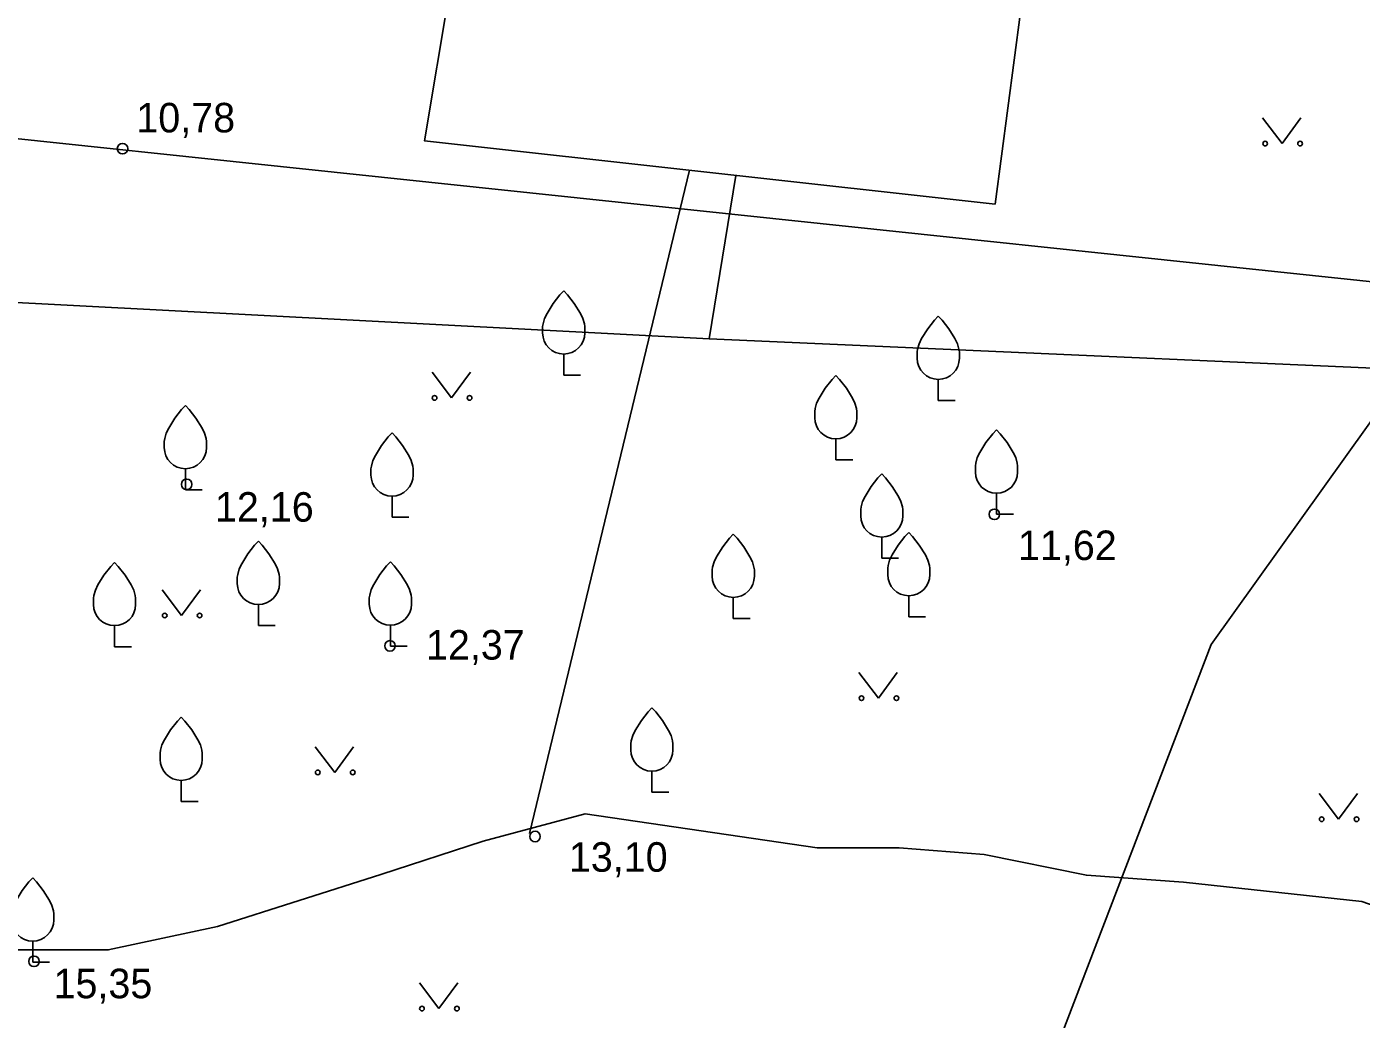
# Model space of a CAD drawing. Extents: x 713497 to 713863, y 6590062 to 6590327.
# Drawn here: x 713803.4 to 713835.04, y 6590273.77 to 6590297.3 of the extents above; entities that cross this region are included whole.
import ezdxf

# ---------------------------------------------------------------- set-up
doc = ezdxf.new("R2010")
doc.units = 0
for name, color, linetype in [('AED', 7, 'Continuous'), ('HALJASTUS', 7, 'Continuous'), ('HOONE', 7, 'Continuous'), ('KORGUS', 7, 'Continuous'), ('KPKAABEL', 7, 'Continuous'), ('PUU', 7, 'Continuous'), ('TTRASS', 7, 'Continuous')]:
    doc.layers.add(name, color=color, linetype=linetype)

msp = doc.modelspace()

# ---------------------------------------------------------------- linework, layer by layer
at = {"layer": 'AED'}
msp.add_lwpolyline([(713815.32, 6590278.17), (713819.11, 6590293.9)], dxfattribs=at)
at = {"layer": 'HALJASTUS'}
for p, q in [((713832.697, 6590295.137), (713833.16, 6590294.53)), ((713833.16, 6590294.53), (713833.606, 6590295.137)), ((713813.007, 6590289.107), (713813.47, 6590288.5)), ((713813.47, 6590288.5), (713813.916, 6590289.107)), ((713806.607, 6590283.947), (713807.07, 6590283.34)), ((713807.07, 6590283.34), (713807.516, 6590283.947)), ((713823.127, 6590281.987), (713823.59, 6590281.38)), ((713823.59, 6590281.38), (713824.036, 6590281.987)), ((713810.237, 6590280.227), (713810.7, 6590279.62)), ((713810.7, 6590279.62), (713811.146, 6590280.227)), ((713834.037, 6590279.117), (713834.5, 6590278.51)), ((713834.5, 6590278.51), (713834.946, 6590279.117)), ((713812.707, 6590274.627), (713813.17, 6590274.02)), ((713813.17, 6590274.02), (713813.616, 6590274.627))]:
    msp.add_line(p, q, dxfattribs=at)
msp.add_lwpolyline([(713835.82, 6590276.29), (713835.05, 6590276.56), (713830.82, 6590277.02), (713828.52, 6590277.18), (713826.1, 6590277.67), (713824.08, 6590277.83), (713822.14, 6590277.83), (713816.64, 6590278.64), (713814.22, 6590277.99), (713811.79, 6590277.2), (713807.92, 6590275.97), (713805.33, 6590275.41), (713802.91, 6590275.41), (713801.86, 6590275.65), (713801.29, 6590275.73), (713800.48, 6590276.13), (713798.54, 6590276.3), (713797.17, 6590276.7), (713794.83, 6590277.43), (713792.28, 6590278.01), (713788.27, 6590278.75)], dxfattribs=at)
for centre in [(713832.759, 6590294.53), (713833.588, 6590294.53), (713813.069, 6590288.5), (713813.898, 6590288.5), (713806.669, 6590283.34), (713807.498, 6590283.34), (713823.189, 6590281.38), (713824.018, 6590281.38), (713810.299, 6590279.62), (713811.128, 6590279.62), (713834.099, 6590278.51), (713834.928, 6590278.51), (713812.769, 6590274.02), (713813.598, 6590274.02)]:
    msp.add_circle(centre, 0.055, dxfattribs=at)
at = {"layer": 'HOONE'}
for points in [[(713826.357, 6590293.093), (713827.26, 6590299.933), (713814.015, 6590301.681), (713812.831, 6590294.592), (713826.357, 6590293.093)], [(713819.58, 6590289.9), (713820.21, 6590293.77)], [(713789.58, 6590291.47), (713819.58, 6590289.9)], [(713819.58, 6590289.9), (713841.05, 6590288.95)]]:
    msp.add_lwpolyline(points, dxfattribs=at)
at = {"layer": 'KORGUS'}
for centre in [(713805.67, 6590294.41), (713807.19, 6590286.45), (713826.34, 6590285.74), (713812.01, 6590282.62), (713815.45, 6590278.1), (713803.57, 6590275.14)]:
    msp.add_circle(centre, 0.125, dxfattribs=at)
at = {"layer": 'KPKAABEL'}
msp.add_lwpolyline([(713863.358, 6590307.496), (713846.983, 6590310.189), (713845.732, 6590309.62), (713844.539, 6590307.426), (713843.803, 6590302.325), (713840.539, 6590295.308), (713831.48, 6590282.65), (713817.48, 6590246.13), (713815.88, 6590242.79)], dxfattribs=at)
at = {"layer": 'PUU'}
for p, q in [((713816.13, 6590289.04), (713816.13, 6590289.54)), ((713816.53, 6590289.04), (713816.13, 6590289.04)), ((713825.01, 6590288.44), (713825.01, 6590288.94)), ((713825.41, 6590288.44), (713825.01, 6590288.44)), ((713822.58, 6590287.03), (713822.58, 6590287.53)), ((713822.98, 6590287.03), (713822.58, 6590287.03)), ((713807.16, 6590286.32), (713807.16, 6590286.82)), ((713807.56, 6590286.32), (713807.16, 6590286.32)), ((713812.06, 6590285.67), (713812.06, 6590286.17)), ((713826.39, 6590285.74), (713826.39, 6590286.24)), ((713826.79, 6590285.74), (713826.39, 6590285.74)), ((713812.46, 6590285.67), (713812.06, 6590285.67)), ((713823.67, 6590284.7), (713823.67, 6590285.2)), ((713824.07, 6590284.7), (713823.67, 6590284.7)), ((713808.89, 6590283.1), (713808.89, 6590283.6)), ((713820.15, 6590283.27), (713820.15, 6590283.77)), ((713824.31, 6590283.31), (713824.31, 6590283.81)), ((713820.55, 6590283.27), (713820.15, 6590283.27)), ((713824.71, 6590283.31), (713824.31, 6590283.31)), ((713805.48, 6590282.6), (713805.48, 6590283.1)), ((713809.29, 6590283.1), (713808.89, 6590283.1)), ((713812.02, 6590282.61), (713812.02, 6590283.11)), ((713805.88, 6590282.6), (713805.48, 6590282.6)), ((713812.42, 6590282.61), (713812.02, 6590282.61)), ((713807.06, 6590278.93), (713807.06, 6590279.43)), ((713818.22, 6590279.15), (713818.22, 6590279.65)), ((713818.62, 6590279.15), (713818.22, 6590279.15)), ((713807.46, 6590278.93), (713807.06, 6590278.93)), ((713803.54, 6590275.12), (713803.54, 6590275.62)), ((713803.94, 6590275.12), (713803.54, 6590275.12))]:
    msp.add_line(p, q, dxfattribs=at)
for points in [[(713815.63, 6590290.04), (713815.63, 6590290.19), (713815.64, 6590290.255), (713815.675, 6590290.385), (713815.735, 6590290.505), (713815.88, 6590290.74), (713816.04, 6590290.945), (713816.13, 6590291.04)], [(713816.63, 6590290.04), (713816.63, 6590290.19), (713816.62, 6590290.255), (713816.585, 6590290.385), (713816.525, 6590290.505), (713816.38, 6590290.74), (713816.22, 6590290.945), (713816.13, 6590291.04)], [(713824.51, 6590289.44), (713824.51, 6590289.59), (713824.52, 6590289.655), (713824.555, 6590289.785), (713824.615, 6590289.905), (713824.76, 6590290.14), (713824.92, 6590290.345), (713825.01, 6590290.44)], [(713825.51, 6590289.44), (713825.51, 6590289.59), (713825.5, 6590289.655), (713825.465, 6590289.785), (713825.405, 6590289.905), (713825.26, 6590290.14), (713825.1, 6590290.345), (713825.01, 6590290.44)], [(713822.08, 6590288.03), (713822.08, 6590288.18), (713822.09, 6590288.245), (713822.125, 6590288.375), (713822.185, 6590288.495), (713822.33, 6590288.73), (713822.49, 6590288.935), (713822.58, 6590289.03)], [(713823.08, 6590288.03), (713823.08, 6590288.18), (713823.07, 6590288.245), (713823.035, 6590288.375), (713822.975, 6590288.495), (713822.83, 6590288.73), (713822.67, 6590288.935), (713822.58, 6590289.03)], [(713806.66, 6590287.32), (713806.66, 6590287.47), (713806.67, 6590287.535), (713806.705, 6590287.665), (713806.765, 6590287.785), (713806.91, 6590288.02), (713807.07, 6590288.225), (713807.16, 6590288.32)], [(713807.66, 6590287.32), (713807.66, 6590287.47), (713807.65, 6590287.535), (713807.615, 6590287.665), (713807.555, 6590287.785), (713807.41, 6590288.02), (713807.25, 6590288.225), (713807.16, 6590288.32)], [(713811.56, 6590286.67), (713811.56, 6590286.82), (713811.57, 6590286.885), (713811.605, 6590287.015), (713811.665, 6590287.135), (713811.81, 6590287.37), (713811.97, 6590287.575), (713812.06, 6590287.67)], [(713812.56, 6590286.67), (713812.56, 6590286.82), (713812.55, 6590286.885), (713812.515, 6590287.015), (713812.455, 6590287.135), (713812.31, 6590287.37), (713812.15, 6590287.575), (713812.06, 6590287.67)], [(713825.89, 6590286.74), (713825.89, 6590286.89), (713825.9, 6590286.955), (713825.935, 6590287.085), (713825.995, 6590287.205), (713826.14, 6590287.44), (713826.3, 6590287.645), (713826.39, 6590287.74)], [(713826.89, 6590286.74), (713826.89, 6590286.89), (713826.88, 6590286.955), (713826.845, 6590287.085), (713826.785, 6590287.205), (713826.64, 6590287.44), (713826.48, 6590287.645), (713826.39, 6590287.74)], [(713823.17, 6590285.7), (713823.17, 6590285.85), (713823.18, 6590285.915), (713823.215, 6590286.045), (713823.275, 6590286.165), (713823.42, 6590286.4), (713823.58, 6590286.605), (713823.67, 6590286.7)], [(713824.17, 6590285.7), (713824.17, 6590285.85), (713824.16, 6590285.915), (713824.125, 6590286.045), (713824.065, 6590286.165), (713823.92, 6590286.4), (713823.76, 6590286.605), (713823.67, 6590286.7)], [(713808.39, 6590284.1), (713808.39, 6590284.25), (713808.4, 6590284.315), (713808.435, 6590284.445), (713808.495, 6590284.565), (713808.64, 6590284.8), (713808.8, 6590285.005), (713808.89, 6590285.1)], [(713809.39, 6590284.1), (713809.39, 6590284.25), (713809.38, 6590284.315), (713809.345, 6590284.445), (713809.285, 6590284.565), (713809.14, 6590284.8), (713808.98, 6590285.005), (713808.89, 6590285.1)], [(713819.65, 6590284.27), (713819.65, 6590284.42), (713819.66, 6590284.485), (713819.695, 6590284.615), (713819.755, 6590284.735), (713819.9, 6590284.97), (713820.06, 6590285.175), (713820.15, 6590285.27)], [(713820.65, 6590284.27), (713820.65, 6590284.42), (713820.64, 6590284.485), (713820.605, 6590284.615), (713820.545, 6590284.735), (713820.4, 6590284.97), (713820.24, 6590285.175), (713820.15, 6590285.27)], [(713823.81, 6590284.31), (713823.81, 6590284.46), (713823.82, 6590284.525), (713823.855, 6590284.655), (713823.915, 6590284.775), (713824.06, 6590285.01), (713824.22, 6590285.215), (713824.31, 6590285.31)], [(713824.81, 6590284.31), (713824.81, 6590284.46), (713824.8, 6590284.525), (713824.765, 6590284.655), (713824.705, 6590284.775), (713824.56, 6590285.01), (713824.4, 6590285.215), (713824.31, 6590285.31)], [(713804.98, 6590283.6), (713804.98, 6590283.75), (713804.99, 6590283.815), (713805.025, 6590283.945), (713805.085, 6590284.065), (713805.23, 6590284.3), (713805.39, 6590284.505), (713805.48, 6590284.6)], [(713805.98, 6590283.6), (713805.98, 6590283.75), (713805.97, 6590283.815), (713805.935, 6590283.945), (713805.875, 6590284.065), (713805.73, 6590284.3), (713805.57, 6590284.505), (713805.48, 6590284.6)], [(713811.52, 6590283.61), (713811.52, 6590283.76), (713811.53, 6590283.825), (713811.565, 6590283.955), (713811.625, 6590284.075), (713811.77, 6590284.31), (713811.93, 6590284.515), (713812.02, 6590284.61)], [(713812.52, 6590283.61), (713812.52, 6590283.76), (713812.51, 6590283.825), (713812.475, 6590283.955), (713812.415, 6590284.075), (713812.27, 6590284.31), (713812.11, 6590284.515), (713812.02, 6590284.61)], [(713817.72, 6590280.15), (713817.72, 6590280.3), (713817.73, 6590280.365), (713817.765, 6590280.495), (713817.825, 6590280.615), (713817.97, 6590280.85), (713818.13, 6590281.055), (713818.22, 6590281.15)], [(713818.72, 6590280.15), (713818.72, 6590280.3), (713818.71, 6590280.365), (713818.675, 6590280.495), (713818.615, 6590280.615), (713818.47, 6590280.85), (713818.31, 6590281.055), (713818.22, 6590281.15)], [(713806.56, 6590279.93), (713806.56, 6590280.08), (713806.57, 6590280.145), (713806.605, 6590280.275), (713806.665, 6590280.395), (713806.81, 6590280.63), (713806.97, 6590280.835), (713807.06, 6590280.93)], [(713807.56, 6590279.93), (713807.56, 6590280.08), (713807.55, 6590280.145), (713807.515, 6590280.275), (713807.455, 6590280.395), (713807.31, 6590280.63), (713807.15, 6590280.835), (713807.06, 6590280.93)], [(713803.04, 6590276.12), (713803.04, 6590276.27), (713803.05, 6590276.335), (713803.085, 6590276.465), (713803.145, 6590276.585), (713803.29, 6590276.82), (713803.45, 6590277.025), (713803.54, 6590277.12)], [(713804.04, 6590276.12), (713804.04, 6590276.27), (713804.03, 6590276.335), (713803.995, 6590276.465), (713803.935, 6590276.585), (713803.79, 6590276.82), (713803.63, 6590277.025), (713803.54, 6590277.12)]]:
    msp.add_lwpolyline(points, dxfattribs=at)
for centre in [(713816.13, 6590290.04), (713825.01, 6590289.44), (713822.58, 6590288.03), (713807.16, 6590287.32), (713826.39, 6590286.74), (713812.06, 6590286.67), (713823.67, 6590285.7), (713820.15, 6590284.27), (713824.31, 6590284.31), (713808.89, 6590284.1), (713805.48, 6590283.6), (713812.02, 6590283.61), (713818.22, 6590280.15), (713807.06, 6590279.93), (713803.54, 6590276.12)]:
    msp.add_arc(centre, 0.5, 180, 0, dxfattribs=at)
at = {"layer": 'TTRASS'}
msp.add_lwpolyline([(713863.358, 6590288.356), (713837.4, 6590291.03), (713795.49, 6590295.46), (713781.73, 6590297.14)], dxfattribs=at)

# ---------------------------------------------------------------- texts
at = {"layer": 'KORGUS'}
for s, p in [('10,78', (713805.996, 6590294.795)), ('12,16', (713807.86, 6590285.565)), ('11,62', (713826.898, 6590284.655)), ('12,37', (713812.863, 6590282.295)), ('13,10', (713816.251, 6590277.265)), ('15,35', (713804.033, 6590274.265))]:
    msp.add_text(s, height=0.7, dxfattribs=at).set_placement(p)

doc.saveas('drawing.dxf')
